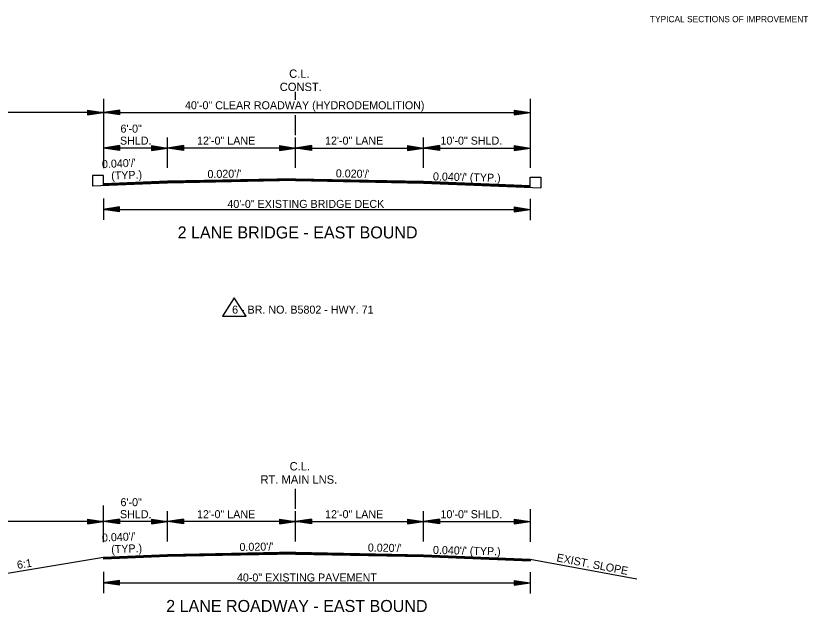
# Model space of a CAD drawing. Extents: x 542112 to 1930787, y -1968972 to 596640.
# Drawn here: x 545013 to 545755, y -1950515 to -1949956 of the extents above; entities that cross this region are included whole.
import ezdxf

# ---------------------------------------------------------------- set-up
doc = ezdxf.new("R2010")
doc.units = 0
for name, color, linetype in [('R_Border', 7, 'Continuous'), ('R_Border Prem', 7, 'Continuous'), ('R_Draft', 7, 'Continuous')]:
    doc.layers.add(name, color=color, linetype=linetype)

msp = doc.modelspace()

# ---------------------------------------------------------------- linework, layer by layer
at = {"layer": 'R_Border'}
for p, q in [((545094.54, -1950106.13), (545084.37, -1950106.13)), ((545084.37, -1950106.13), (545084.37, -1950115.94)), ((545094.54, -1950115.53), (545094.54, -1950106.13)), ((545494.54, -1950117.13), (545494.54, -1950107.73)), ((545494.54, -1950107.73), (545504.71, -1950107.73)), ((545504.71, -1950107.73), (545504.71, -1950117.54)), ((545217.27, -1950220.64), (545206.23, -1950237.94)), ((545228.31, -1950237.94), (545217.27, -1950220.64)), ((545206.23, -1950237.94), (545228.31, -1950237.94))]:
    msp.add_line(p, q, dxfattribs=at)
at = {"layer": 'R_Draft'}
for p, q in [((545274.54, -1950035.03), (545274.54, -1950027.6)), ((545094.54, -1950034.21), (545094.54, -1950099.09)), ((545494.54, -1950034.21), (545494.54, -1950098.92)), ((545079.54, -1950044.72), (545094.54, -1950046.97)), ((545079.54, -1950044.72), (545079.54, -1950049.22)), ((545109.89, -1950044.72), (545094.89, -1950046.97)), ((545109.89, -1950049.22), (545109.89, -1950044.72)), ((545479.54, -1950044.72), (545494.54, -1950046.97)), ((545479.54, -1950044.72), (545479.54, -1950049.22)), ((545094.54, -1950046.97), (544794.54, -1950046.97)), ((545079.54, -1950045.09), (545092.04, -1950046.97)), ((545079.54, -1950045.47), (545089.46, -1950046.97)), ((545079.54, -1950045.85), (545086.96, -1950046.97)), ((545079.54, -1950046.24), (545084.42, -1950046.97)), ((545079.54, -1950046.61), (545081.91, -1950046.97)), ((545079.54, -1950049.22), (545094.54, -1950046.97)), ((545079.54, -1950047.7), (545084.42, -1950046.97)), ((545079.54, -1950048.46), (545089.46, -1950046.97)), ((545079.54, -1950048.84), (545092.04, -1950046.97)), ((545079.54, -1950048.08), (545086.96, -1950046.97)), ((545079.54, -1950047.32), (545081.91, -1950046.97)), ((545094.54, -1950046.97), (545494.54, -1950046.97)), ((545109.89, -1950049.22), (545094.89, -1950046.97)), ((545109.89, -1950045.09), (545097.39, -1950046.97)), ((545109.89, -1950048.84), (545097.39, -1950046.97)), ((545109.89, -1950045.47), (545099.97, -1950046.97)), ((545109.89, -1950048.46), (545099.97, -1950046.97)), ((545109.89, -1950045.85), (545102.47, -1950046.97)), ((545109.89, -1950048.08), (545102.47, -1950046.97)), ((545109.89, -1950046.23), (545105.01, -1950046.97)), ((545109.89, -1950047.69), (545105.01, -1950046.97)), ((545109.89, -1950046.61), (545107.52, -1950046.97)), ((545109.89, -1950047.32), (545107.52, -1950046.97)), ((545274.54, -1950068.24), (545274.54, -1950049.55)), ((545479.54, -1950045.09), (545492.04, -1950046.97)), ((545479.54, -1950045.47), (545489.46, -1950046.97)), ((545479.54, -1950045.85), (545486.96, -1950046.97)), ((545479.54, -1950046.24), (545484.42, -1950046.97)), ((545479.54, -1950046.61), (545481.91, -1950046.97)), ((545479.54, -1950049.22), (545494.54, -1950046.97)), ((545479.54, -1950047.7), (545484.42, -1950046.97)), ((545479.54, -1950048.46), (545489.46, -1950046.97)), ((545479.54, -1950048.84), (545492.04, -1950046.97)), ((545479.54, -1950048.08), (545486.96, -1950046.97)), ((545479.54, -1950047.32), (545481.91, -1950046.97)), ((545154.54, -1950098.92), (545154.54, -1950070.37)), ((545274.54, -1950098.92), (545274.54, -1950070.37)), ((545394.54, -1950098.92), (545394.54, -1950070.37)), ((545109.54, -1950078.01), (545094.54, -1950080.26)), ((545154.54, -1950080.26), (545094.54, -1950080.26)), ((545109.54, -1950082.51), (545094.54, -1950080.26)), ((545109.54, -1950078.39), (545097.05, -1950080.26)), ((545109.54, -1950082.14), (545097.05, -1950080.26)), ((545109.54, -1950078.77), (545099.63, -1950080.26)), ((545109.54, -1950081.75), (545099.63, -1950080.26)), ((545109.54, -1950079.14), (545102.12, -1950080.26)), ((545109.54, -1950081.38), (545102.12, -1950080.26)), ((545109.54, -1950079.53), (545104.67, -1950080.26)), ((545109.54, -1950081), (545104.67, -1950080.26)), ((545109.54, -1950079.91), (545107.17, -1950080.26)), ((545109.54, -1950080.61), (545107.17, -1950080.26)), ((545109.54, -1950078.01), (545109.54, -1950082.51)), ((545139.54, -1950078.01), (545154.54, -1950080.26)), ((545139.54, -1950078.01), (545139.54, -1950082.51)), ((545139.54, -1950078.39), (545152.04, -1950080.26)), ((545139.54, -1950078.77), (545149.46, -1950080.26)), ((545139.54, -1950079.14), (545146.96, -1950080.26)), ((545139.54, -1950079.53), (545144.42, -1950080.26)), ((545139.54, -1950079.91), (545141.91, -1950080.26)), ((545139.54, -1950082.51), (545154.54, -1950080.26)), ((545139.54, -1950081), (545144.42, -1950080.26)), ((545139.54, -1950081.75), (545149.46, -1950080.26)), ((545139.54, -1950082.14), (545152.04, -1950080.26)), ((545139.54, -1950081.38), (545146.96, -1950080.26)), ((545139.54, -1950080.61), (545141.91, -1950080.26)), ((545169.54, -1950078.01), (545154.54, -1950080.26)), ((545274.54, -1950080.26), (545154.54, -1950080.26)), ((545169.54, -1950082.51), (545154.54, -1950080.26)), ((545169.54, -1950078.39), (545157.05, -1950080.26)), ((545169.54, -1950082.14), (545157.05, -1950080.26)), ((545169.54, -1950078.77), (545159.63, -1950080.26)), ((545169.54, -1950081.75), (545159.63, -1950080.26)), ((545169.54, -1950079.14), (545162.12, -1950080.26)), ((545169.54, -1950081.38), (545162.12, -1950080.26)), ((545169.54, -1950079.53), (545164.67, -1950080.26)), ((545169.54, -1950081), (545164.67, -1950080.26)), ((545169.54, -1950079.91), (545167.17, -1950080.26)), ((545169.54, -1950080.61), (545167.17, -1950080.26)), ((545169.54, -1950078.01), (545169.54, -1950082.51)), ((545259.54, -1950078.01), (545274.54, -1950080.26)), ((545259.54, -1950078.01), (545259.54, -1950082.51)), ((545259.54, -1950078.39), (545272.04, -1950080.26)), ((545259.54, -1950078.77), (545269.46, -1950080.26)), ((545259.54, -1950079.14), (545266.96, -1950080.26)), ((545259.54, -1950079.53), (545264.42, -1950080.26)), ((545259.54, -1950079.91), (545261.91, -1950080.26)), ((545259.54, -1950082.51), (545274.54, -1950080.26)), ((545259.54, -1950081), (545264.42, -1950080.26)), ((545259.54, -1950081.75), (545269.46, -1950080.26)), ((545259.54, -1950082.14), (545272.04, -1950080.26)), ((545259.54, -1950081.38), (545266.96, -1950080.26)), ((545259.54, -1950080.61), (545261.91, -1950080.26)), ((545289.54, -1950078.01), (545274.54, -1950080.26)), ((545289.54, -1950082.51), (545274.54, -1950080.26)), ((545274.54, -1950080.26), (545394.54, -1950080.26)), ((545289.54, -1950078.39), (545277.05, -1950080.26)), ((545289.54, -1950082.14), (545277.05, -1950080.26)), ((545289.54, -1950078.77), (545279.63, -1950080.26)), ((545289.54, -1950081.75), (545279.63, -1950080.26)), ((545289.54, -1950079.14), (545282.12, -1950080.26)), ((545289.54, -1950081.38), (545282.12, -1950080.26)), ((545289.54, -1950079.53), (545284.67, -1950080.26)), ((545289.54, -1950081), (545284.67, -1950080.26)), ((545289.54, -1950079.91), (545287.17, -1950080.26)), ((545289.54, -1950080.61), (545287.17, -1950080.26)), ((545289.54, -1950078.01), (545289.54, -1950082.51)), ((545379.54, -1950078.01), (545394.54, -1950080.26)), ((545379.54, -1950078.01), (545379.54, -1950082.51)), ((545379.54, -1950078.39), (545392.04, -1950080.26)), ((545379.54, -1950078.77), (545389.46, -1950080.26)), ((545379.54, -1950079.14), (545386.96, -1950080.26)), ((545379.54, -1950079.53), (545384.42, -1950080.26)), ((545379.54, -1950079.91), (545381.91, -1950080.26)), ((545379.54, -1950082.51), (545394.54, -1950080.26)), ((545379.54, -1950081), (545384.42, -1950080.26)), ((545379.54, -1950081.75), (545389.46, -1950080.26)), ((545379.54, -1950082.14), (545392.04, -1950080.26)), ((545379.54, -1950081.38), (545386.96, -1950080.26)), ((545379.54, -1950080.61), (545381.91, -1950080.26)), ((545409.54, -1950078.01), (545394.54, -1950080.26)), ((545394.54, -1950080.26), (545494.54, -1950080.26)), ((545409.54, -1950082.51), (545394.54, -1950080.26)), ((545409.54, -1950078.39), (545397.05, -1950080.26)), ((545409.54, -1950082.14), (545397.05, -1950080.26)), ((545409.54, -1950078.77), (545399.63, -1950080.26)), ((545409.54, -1950081.75), (545399.63, -1950080.26)), ((545409.54, -1950079.14), (545402.12, -1950080.26)), ((545409.54, -1950081.38), (545402.12, -1950080.26)), ((545409.54, -1950079.53), (545404.67, -1950080.26)), ((545409.54, -1950081), (545404.67, -1950080.26)), ((545409.54, -1950079.91), (545407.17, -1950080.26)), ((545409.54, -1950080.61), (545407.17, -1950080.26)), ((545409.54, -1950078.01), (545409.54, -1950082.51)), ((545479.54, -1950078.01), (545494.54, -1950080.26)), ((545479.54, -1950078.01), (545479.54, -1950082.51)), ((545479.54, -1950078.39), (545492.04, -1950080.26)), ((545479.54, -1950078.77), (545489.46, -1950080.26)), ((545479.54, -1950079.14), (545486.96, -1950080.26)), ((545479.54, -1950079.53), (545484.42, -1950080.26)), ((545479.54, -1950079.91), (545481.91, -1950080.26)), ((545479.54, -1950082.51), (545494.54, -1950080.26)), ((545479.54, -1950081), (545484.42, -1950080.26)), ((545479.54, -1950081.75), (545489.46, -1950080.26)), ((545479.54, -1950082.14), (545492.04, -1950080.26)), ((545479.54, -1950081.38), (545486.96, -1950080.26)), ((545479.54, -1950080.61), (545481.91, -1950080.26)), ((545154.54, -1950111.47), (545094.54, -1950113.87)), ((545274.54, -1950109.07), (545154.54, -1950111.47)), ((545274.54, -1950109.37), (545154.54, -1950111.77)), ((545274.54, -1950109.67), (545154.54, -1950112.07)), ((545274.54, -1950109.97), (545154.54, -1950112.37)), ((545274.54, -1950110.27), (545154.54, -1950112.67)), ((545274.54, -1950110.57), (545154.54, -1950112.97)), ((545274.54, -1950110.73), (545154.54, -1950113.13)), ((545274.54, -1950109.07), (545394.54, -1950111.47)), ((545274.54, -1950109.37), (545394.54, -1950111.77)), ((545274.54, -1950109.67), (545394.54, -1950112.07)), ((545274.54, -1950109.97), (545394.54, -1950112.37)), ((545274.54, -1950110.27), (545394.54, -1950112.67)), ((545274.54, -1950110.57), (545394.54, -1950112.97)), ((545274.54, -1950110.73), (545394.54, -1950113.13)), ((545394.54, -1950111.47), (545494.54, -1950115.47)), ((545154.61, -1950113.13), (545084.37, -1950115.94)), ((545154.55, -1950111.77), (545094.54, -1950114.17)), ((545154.56, -1950112.07), (545094.54, -1950114.47)), ((545154.57, -1950112.37), (545094.54, -1950114.77)), ((545154.58, -1950112.67), (545094.54, -1950115.07)), ((545154.59, -1950112.97), (545094.54, -1950115.37)), ((545394.54, -1950111.77), (545494.54, -1950115.77)), ((545394.54, -1950112.07), (545494.54, -1950116.07)), ((545394.54, -1950112.37), (545494.54, -1950116.37)), ((545394.54, -1950112.67), (545494.54, -1950116.67)), ((545394.54, -1950112.97), (545494.54, -1950116.97)), ((545394.54, -1950113.13), (545504.71, -1950117.54)), ((545094.54, -1950127.48), (545094.54, -1950147.48)), ((545494.54, -1950127.8), (545494.54, -1950147.8)), ((545109.53, -1950135.47), (545094.53, -1950137.72)), ((545109.53, -1950139.97), (545094.53, -1950137.72)), ((545094.54, -1950137.72), (545494.54, -1950137.72)), ((545109.53, -1950135.85), (545097.03, -1950137.72)), ((545109.53, -1950139.6), (545097.03, -1950137.72)), ((545109.53, -1950136.23), (545099.61, -1950137.72)), ((545109.53, -1950139.22), (545099.61, -1950137.72)), ((545109.53, -1950136.61), (545102.11, -1950137.72)), ((545109.53, -1950138.84), (545102.11, -1950137.72)), ((545109.53, -1950136.99), (545104.65, -1950137.72)), ((545109.53, -1950138.45), (545104.65, -1950137.72)), ((545109.53, -1950137.37), (545107.16, -1950137.72)), ((545109.53, -1950138.08), (545107.16, -1950137.72)), ((545109.53, -1950139.97), (545109.53, -1950135.47)), ((545479.54, -1950135.47), (545494.54, -1950137.72)), ((545479.54, -1950135.47), (545479.54, -1950139.97)), ((545479.54, -1950135.85), (545492.04, -1950137.72)), ((545479.54, -1950136.23), (545489.46, -1950137.72)), ((545479.54, -1950136.61), (545486.96, -1950137.72)), ((545479.54, -1950137), (545484.42, -1950137.72)), ((545479.54, -1950137.37), (545481.91, -1950137.72)), ((545479.54, -1950139.97), (545494.54, -1950137.72)), ((545479.54, -1950138.46), (545484.42, -1950137.72)), ((545479.54, -1950139.22), (545489.46, -1950137.72)), ((545479.54, -1950139.6), (545492.04, -1950137.72)), ((545479.54, -1950138.84), (545486.96, -1950137.72)), ((545479.54, -1950138.08), (545481.91, -1950137.72)), ((545274.54, -1950418.24), (545274.54, -1950399.55)), ((545094.34, -1950415.3), (545094.34, -1950449.48)), ((545154.54, -1950448.92), (545154.54, -1950420.37)), ((545274.54, -1950448.92), (545274.54, -1950420.37)), ((545394.54, -1950448.92), (545394.54, -1950420.37)), ((545494.54, -1950418.77), (545494.54, -1950449.31)), ((545094.54, -1950430.26), (544794.54, -1950430.26)), ((545079.54, -1950428.01), (545094.54, -1950430.26)), ((545079.54, -1950428.01), (545079.54, -1950432.51)), ((545079.54, -1950428.39), (545092.04, -1950430.26)), ((545079.54, -1950428.77), (545089.46, -1950430.26)), ((545079.54, -1950429.14), (545086.96, -1950430.26)), ((545079.54, -1950429.53), (545084.42, -1950430.26)), ((545079.54, -1950429.91), (545081.91, -1950430.26)), ((545079.54, -1950432.51), (545094.54, -1950430.26)), ((545079.54, -1950431), (545084.42, -1950430.26)), ((545079.54, -1950431.75), (545089.46, -1950430.26)), ((545079.54, -1950432.14), (545092.04, -1950430.26)), ((545079.54, -1950431.38), (545086.96, -1950430.26)), ((545079.54, -1950430.61), (545081.91, -1950430.26)), ((545109.54, -1950428.01), (545094.54, -1950430.26)), ((545154.54, -1950430.26), (545094.54, -1950430.26)), ((545109.54, -1950432.51), (545094.54, -1950430.26)), ((545109.54, -1950428.39), (545097.05, -1950430.26)), ((545109.54, -1950432.14), (545097.05, -1950430.26)), ((545109.54, -1950428.77), (545099.63, -1950430.26)), ((545109.54, -1950431.75), (545099.63, -1950430.26)), ((545109.54, -1950429.14), (545102.12, -1950430.26)), ((545109.54, -1950431.38), (545102.12, -1950430.26)), ((545109.54, -1950429.53), (545104.67, -1950430.26)), ((545109.54, -1950431), (545104.67, -1950430.26)), ((545109.54, -1950429.91), (545107.17, -1950430.26)), ((545109.54, -1950430.61), (545107.17, -1950430.26)), ((545109.54, -1950428.01), (545109.54, -1950432.51)), ((545139.54, -1950428.01), (545154.54, -1950430.26)), ((545139.54, -1950428.01), (545139.54, -1950432.51)), ((545139.54, -1950428.39), (545152.04, -1950430.26)), ((545139.54, -1950428.77), (545149.46, -1950430.26)), ((545139.54, -1950429.14), (545146.96, -1950430.26)), ((545139.54, -1950429.53), (545144.42, -1950430.26)), ((545139.54, -1950429.91), (545141.91, -1950430.26)), ((545139.54, -1950432.51), (545154.54, -1950430.26)), ((545139.54, -1950431), (545144.42, -1950430.26)), ((545139.54, -1950431.75), (545149.46, -1950430.26)), ((545139.54, -1950432.14), (545152.04, -1950430.26)), ((545139.54, -1950431.38), (545146.96, -1950430.26)), ((545139.54, -1950430.61), (545141.91, -1950430.26)), ((545169.54, -1950428.01), (545154.54, -1950430.26)), ((545274.54, -1950430.26), (545154.54, -1950430.26)), ((545169.54, -1950432.51), (545154.54, -1950430.26)), ((545169.54, -1950428.39), (545157.05, -1950430.26)), ((545169.54, -1950432.14), (545157.05, -1950430.26)), ((545169.54, -1950428.77), (545159.63, -1950430.26)), ((545169.54, -1950431.75), (545159.63, -1950430.26)), ((545169.54, -1950429.14), (545162.12, -1950430.26)), ((545169.54, -1950431.38), (545162.12, -1950430.26)), ((545169.54, -1950429.53), (545164.67, -1950430.26)), ((545169.54, -1950431), (545164.67, -1950430.26)), ((545169.54, -1950429.91), (545167.17, -1950430.26)), ((545169.54, -1950430.61), (545167.17, -1950430.26)), ((545169.54, -1950428.01), (545169.54, -1950432.51)), ((545259.54, -1950428.01), (545274.54, -1950430.26)), ((545259.54, -1950428.01), (545259.54, -1950432.51)), ((545259.54, -1950428.39), (545272.04, -1950430.26)), ((545259.54, -1950428.77), (545269.46, -1950430.26)), ((545259.54, -1950429.14), (545266.96, -1950430.26)), ((545259.54, -1950429.53), (545264.42, -1950430.26)), ((545259.54, -1950429.91), (545261.91, -1950430.26)), ((545259.54, -1950432.51), (545274.54, -1950430.26)), ((545259.54, -1950431), (545264.42, -1950430.26)), ((545259.54, -1950431.75), (545269.46, -1950430.26)), ((545259.54, -1950432.14), (545272.04, -1950430.26)), ((545259.54, -1950431.38), (545266.96, -1950430.26)), ((545259.54, -1950430.61), (545261.91, -1950430.26)), ((545289.54, -1950428.01), (545274.54, -1950430.26)), ((545289.54, -1950432.51), (545274.54, -1950430.26)), ((545274.54, -1950430.26), (545394.54, -1950430.26)), ((545289.54, -1950428.39), (545277.05, -1950430.26)), ((545289.54, -1950432.14), (545277.05, -1950430.26)), ((545289.54, -1950428.77), (545279.63, -1950430.26)), ((545289.54, -1950431.75), (545279.63, -1950430.26)), ((545289.54, -1950429.14), (545282.12, -1950430.26)), ((545289.54, -1950431.38), (545282.12, -1950430.26)), ((545289.54, -1950429.53), (545284.67, -1950430.26)), ((545289.54, -1950431), (545284.67, -1950430.26)), ((545289.54, -1950429.91), (545287.17, -1950430.26)), ((545289.54, -1950430.61), (545287.17, -1950430.26)), ((545289.54, -1950428.01), (545289.54, -1950432.51)), ((545379.54, -1950428.01), (545394.54, -1950430.26)), ((545379.54, -1950428.01), (545379.54, -1950432.51)), ((545379.54, -1950428.39), (545392.04, -1950430.26)), ((545379.54, -1950428.77), (545389.46, -1950430.26)), ((545379.54, -1950429.14), (545386.96, -1950430.26)), ((545379.54, -1950429.53), (545384.42, -1950430.26)), ((545379.54, -1950429.91), (545381.91, -1950430.26)), ((545379.54, -1950432.51), (545394.54, -1950430.26)), ((545379.54, -1950431), (545384.42, -1950430.26)), ((545379.54, -1950431.75), (545389.46, -1950430.26)), ((545379.54, -1950432.14), (545392.04, -1950430.26)), ((545379.54, -1950431.38), (545386.96, -1950430.26)), ((545379.54, -1950430.61), (545381.91, -1950430.26)), ((545409.54, -1950428.01), (545394.54, -1950430.26)), ((545394.54, -1950430.26), (545494.54, -1950430.26)), ((545409.54, -1950432.51), (545394.54, -1950430.26)), ((545409.54, -1950428.39), (545397.05, -1950430.26)), ((545409.54, -1950432.14), (545397.05, -1950430.26)), ((545409.54, -1950428.77), (545399.63, -1950430.26)), ((545409.54, -1950431.75), (545399.63, -1950430.26)), ((545409.54, -1950429.14), (545402.12, -1950430.26)), ((545409.54, -1950431.38), (545402.12, -1950430.26)), ((545409.54, -1950429.53), (545404.67, -1950430.26)), ((545409.54, -1950431), (545404.67, -1950430.26)), ((545409.54, -1950429.91), (545407.17, -1950430.26)), ((545409.54, -1950430.61), (545407.17, -1950430.26)), ((545409.54, -1950428.01), (545409.54, -1950432.51)), ((545479.54, -1950428.01), (545494.54, -1950430.26)), ((545479.54, -1950428.01), (545479.54, -1950432.51)), ((545479.54, -1950428.39), (545492.04, -1950430.26)), ((545479.54, -1950428.77), (545489.46, -1950430.26)), ((545479.54, -1950429.14), (545486.96, -1950430.26)), ((545479.54, -1950429.53), (545484.42, -1950430.26)), ((545479.54, -1950429.91), (545481.91, -1950430.26)), ((545479.54, -1950432.51), (545494.54, -1950430.26)), ((545479.54, -1950431), (545484.42, -1950430.26)), ((545479.54, -1950431.75), (545489.46, -1950430.26)), ((545479.54, -1950432.14), (545492.04, -1950430.26)), ((545479.54, -1950431.38), (545486.96, -1950430.26)), ((545479.54, -1950430.61), (545481.91, -1950430.26)), ((545274.54, -1950459.07), (545154.54, -1950461.47)), ((545274.54, -1950459.37), (545154.54, -1950461.77)), ((545274.54, -1950459.67), (545154.54, -1950462.07)), ((545274.54, -1950459.97), (545154.54, -1950462.37)), ((545274.54, -1950460.27), (545154.54, -1950462.67)), ((545274.54, -1950460.57), (545154.54, -1950462.97)), ((545274.54, -1950459.07), (545394.54, -1950461.47)), ((545274.54, -1950459.37), (545394.54, -1950461.77)), ((545274.54, -1950459.67), (545394.54, -1950462.07)), ((545274.54, -1950459.97), (545394.54, -1950462.37)), ((545274.54, -1950460.27), (545394.54, -1950462.67)), ((545274.54, -1950460.57), (545394.54, -1950462.97)), ((545094.54, -1950463.87), (544944.54, -1950488.87)), ((545154.54, -1950461.47), (545094.54, -1950463.87)), ((545154.55, -1950461.77), (545094.54, -1950464.17)), ((545154.56, -1950462.07), (545094.54, -1950464.47)), ((545154.57, -1950462.37), (545094.54, -1950464.77)), ((545154.58, -1950462.67), (545094.54, -1950465.07)), ((545154.59, -1950462.97), (545094.54, -1950465.37)), ((545154.61, -1950463.13), (545094.54, -1950465.53)), ((545094.54, -1950463.87), (545094.54, -1950465.53)), ((545274.54, -1950460.73), (545154.54, -1950463.13)), ((545274.54, -1950460.73), (545394.54, -1950463.13)), ((545394.54, -1950461.47), (545494.54, -1950465.47)), ((545394.54, -1950461.77), (545494.54, -1950465.77)), ((545394.54, -1950462.07), (545494.54, -1950466.07)), ((545394.54, -1950462.37), (545494.54, -1950466.37)), ((545394.54, -1950462.67), (545494.54, -1950466.67)), ((545394.54, -1950462.97), (545494.54, -1950466.97)), ((545394.54, -1950463.13), (545494.54, -1950467.13)), ((545494.54, -1950465.47), (545594.61, -1950483.84)), ((545494.54, -1950465.47), (545494.54, -1950467.13)), ((545094.54, -1950477.48), (545094.54, -1950497.48)), ((545494.54, -1950477.8), (545494.54, -1950497.8)), ((545109.53, -1950485.47), (545094.53, -1950487.72)), ((545109.53, -1950489.97), (545094.53, -1950487.72)), ((545094.54, -1950487.72), (545494.54, -1950487.72)), ((545109.53, -1950485.85), (545097.03, -1950487.72)), ((545109.53, -1950489.6), (545097.03, -1950487.72)), ((545109.53, -1950486.23), (545099.61, -1950487.72)), ((545109.53, -1950489.22), (545099.61, -1950487.72)), ((545109.53, -1950486.61), (545102.11, -1950487.72)), ((545109.53, -1950488.84), (545102.11, -1950487.72)), ((545109.53, -1950486.99), (545104.65, -1950487.72)), ((545109.53, -1950488.45), (545104.65, -1950487.72)), ((545109.53, -1950487.37), (545107.16, -1950487.72)), ((545109.53, -1950488.08), (545107.16, -1950487.72)), ((545109.53, -1950489.97), (545109.53, -1950485.47)), ((545479.54, -1950485.47), (545494.54, -1950487.72)), ((545479.54, -1950485.47), (545479.54, -1950489.97)), ((545479.54, -1950485.85), (545492.04, -1950487.72)), ((545479.54, -1950486.23), (545489.46, -1950487.72)), ((545479.54, -1950486.61), (545486.96, -1950487.72)), ((545479.54, -1950487), (545484.42, -1950487.72)), ((545479.54, -1950487.37), (545481.91, -1950487.72)), ((545479.54, -1950489.97), (545494.54, -1950487.72)), ((545479.54, -1950488.46), (545484.42, -1950487.72)), ((545479.54, -1950489.22), (545489.46, -1950487.72)), ((545479.54, -1950489.6), (545492.04, -1950487.72)), ((545479.54, -1950488.84), (545486.96, -1950487.72)), ((545479.54, -1950488.08), (545481.91, -1950487.72))]:
    msp.add_line(p, q, dxfattribs=at)

# ---------------------------------------------------------------- texts
at = {"layer": 'R_Border Prem'}
msp.add_text('TYPICAL SECTIONS OF IMPROVEMENT', height=5.862, rotation=360, dxfattribs=at).set_placement((545606.81, -1949962.39))
at = {"layer": 'R_Draft'}
for s, height, p in [('C.L.', 7.8, (545268.7, -1950014.51)), ('CONST.', 7.8, (545259.91, -1950026.88)), ('40\'-0" CLEAR ROADWAY (HYDRODEMOLITION)', 7.5, (545171.06, -1950043.95)), ('6\'-0" ', 7.5, (545110.63, -1950065.84)), ('SHLD.', 7.5, (545110.13, -1950077.09)), ('12\'-0" LANE', 7.5, (545182.36, -1950077.09)), ('12\'-0" LANE', 7.5, (545302.36, -1950077.09)), ('10\'-0" SHLD.', 7.5, (545410.53, -1950077.09)), ('40\'-0" EXISTING BRIDGE DECK', 7.5, (545210.8, -1950136.4)), ('2 LANE BRIDGE - EAST BOUND', 11.25, (545164.19, -1950164.97)), ('6 - BR. NO. B5802 - HWY. 71', 7.5, (545215.23, -1950235.43)), ('C.L.', 7.8, (545269.13, -1950382.36)), ('RT. MAIN LNS.', 7.8, (545241.88, -1950394.73)), ('6\'-0" ', 7.5, (545110.63, -1950415.84)), ('SHLD.', 7.5, (545110.13, -1950427.09)), ('12\'-0" LANE', 7.5, (545182.36, -1950427.09)), ('12\'-0" LANE', 7.5, (545302.36, -1950427.09)), ('10\'-0" SHLD.', 7.5, (545410.53, -1950427.09)), ('40-0" EXISTING PAVEMENT', 7.5, (545219.75, -1950486.4)), ('2 LANE ROADWAY - EAST BOUND', 11.25, (545153.47, -1950514.97))]:
    msp.add_text(s, height=height, dxfattribs=at).set_placement(p)
for s, rotation, p in [("  0.040'/'", 2.44797, (545087.84, -1950099.34)), (' (TYP.)', 2.44797, (545099.26, -1950110.12)), ("0.020'/'", 0.97192, (545192.19, -1950108.45)), ("0.020'/'", 359.02808, (545312.37, -1950107.7)), ("0.040'/' (TYP.)", 358.68162, (545403.43, -1950110.54)), ("  0.040'/'", 2.44797, (545087.84, -1950449.34)), (' (TYP.)', 2.44797, (545099.26, -1950460.12)), ("0.020'/'", 0.97192, (545222.19, -1950457.85)), ("0.020'/'", 359.02808, (545342.37, -1950458.3)), ("0.040'/' (TYP.)", 358.68162, (545403.43, -1950460.54)), ('EXIST. SLOPE', 349.11714, (545518.92, -1950467.46)), ('6:1', 9.15344, (545014.23, -1950474.7))]:
    msp.add_text(s, height=7.5, rotation=rotation, dxfattribs=at).set_placement(p)

doc.saveas('drawing.dxf')
